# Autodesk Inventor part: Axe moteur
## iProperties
Shininess: 64.0
Length Units: 11269
Angle Units: 11279
Time Units: 11290
Mass Units: 11283
Length Display Precision: 3
Angle Display Precision: 2
Compacted: True
Part Number: Axe moteur
Document SubType Name: Modeling
Created: 2005-01
Material: Par défaut
Designer: Flavien MARTY
Density: 0.0
Volumn: 0.0
Area: 0.0
PropertySet Name: Model Information
Control State: 0
Master: False
Checked Out: False
Norme de conversion: STEP AP203
Nom du fichier: Axe moteur.STEP
Préprocesseur: SolidWorks 2001039
Postprocesseur: Build: Release: 6 RTM Build: 90b - Date: Tue 09/24/2002
Unités envoyées: MILLIMETERS
Incertitude: 0.0
Author: Flavien MARTY
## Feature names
1. Base1
